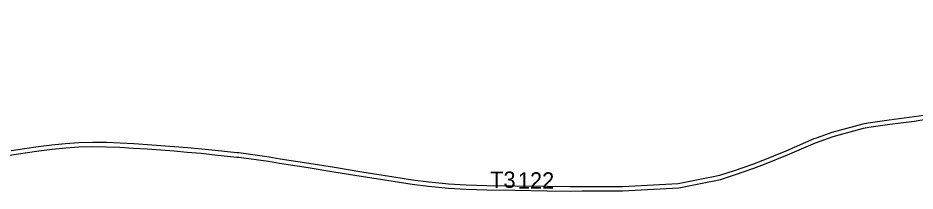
# Model space of a CAD drawing. Extents: x -477001 to -465642, y -1158278 to -1150672.
# Drawn here: x -470657 to -469997, y -1153800 to -1153673 of the extents above; entities that cross this region are included whole.
import ezdxf

# ---------------------------------------------------------------- set-up
doc = ezdxf.new("R2010")
doc.units = 0
for name, color, linetype in [('VPS_id', 7, 'Continuous'), ('VPS_n', 7, 'Continuous'), ('vyvlastneni_n', 7, 'Continuous')]:
    doc.layers.add(name, color=color, linetype=linetype)

msp = doc.modelspace()

# ---------------------------------------------------------------- linework, layer by layer
at = {"layer": 'VPS_n'}
for p, q in [((-470069.83, -1153760.86), (-470071.56, -1153761.53)), ((-470063.02, -1153758.53), (-470069.83, -1153760.86)), ((-470652.22, -1153768.74), (-470662.1, -1153770.15)), ((-470592.07, -1153767.18), (-470582.08, -1153767.55)), ((-470571.91, -1153765.17), (-470581.93, -1153764.55)), ((-470561.91, -1153765.85), (-470571.91, -1153765.17)), ((-470551.93, -1153766.56), (-470561.91, -1153765.85)), ((-470541.93, -1153767.33), (-470551.93, -1153766.56)), ((-470532.45, -1153768.12), (-470541.93, -1153767.33)), ((-470521.96, -1153769.04), (-470532.45, -1153768.12)), ((-470562.12, -1153768.84), (-470552.15, -1153769.55)), ((-470552.15, -1153769.55), (-470542.17, -1153770.32)), ((-470542.17, -1153770.32), (-470532.71, -1153771.11)), ((-470511.98, -1153770.09), (-470521.96, -1153769.04)), ((-470472.42, -1153774.91), (-470494.57, -1153771.77)), ((-470464.16, -1153776.25), (-470472.42, -1153774.91)), ((-470443.18, -1153779.56), (-470464.16, -1153776.25)), ((-470424.21, -1153782.59), (-470443.18, -1153779.56)), ((-470381.15, -1153792.57), (-470367.2, -1153794.75)), ((-470354.83, -1153793.23), (-470366.79, -1153791.78)), ((-470342.66, -1153794.46), (-470354.83, -1153793.23)), ((-470340.28, -1153794.65), (-470342.66, -1153794.46)), ((-470327.5, -1153798.46), (-470312.32, -1153798.89)), ((-470312.32, -1153798.89), (-470291.63, -1153799.22)), ((-470291.63, -1153799.22), (-470267.7, -1153799.53)), ((-470267.7, -1153799.53), (-470250.88, -1153799.74)), ((-470250.86, -1153796.74), (-470267.66, -1153796.53))]:
    msp.add_line(p, q, dxfattribs=at)
for points in [[(-470144.94, -1153792.24), (-470140.23, -1153791.32), (-470129.3, -1153787.64), (-470115.74, -1153783.08), (-470108.03, -1153780.1), (-470091.01, -1153773.14), (-470070.47, -1153764.33), (-470057.45, -1153759.75), (-470035.04, -1153753.64), (-470031.12, -1153752.97), (-470015.72, -1153750.56), (-469997.47, -1153748.33), (-469993.57, -1153747.76), (-469959.11, -1153742.5), (-469955.04, -1153741.64), (-469927.41, -1153736.82), (-469911.9, -1153729.32), (-469906.07, -1153723.14), (-469899.47, -1153716.14), (-469892.68, -1153703.71), (-469880.94, -1153672.67)], [(-469962.14, -1153739.93), (-469994.02, -1153744.79), (-469997.87, -1153745.36), (-470016.13, -1153747.59), (-470031.6, -1153750.01), (-470035.69, -1153750.71), (-470058.34, -1153756.88), (-470063.02, -1153758.53)], [(-470071.56, -1153761.53), (-470092.17, -1153770.37), (-470109.14, -1153777.31), (-470116.76, -1153780.26), (-470130.26, -1153784.8), (-470141, -1153788.41), (-470145.52, -1153789.3)], [(-470669.12, -1153774.05), (-470661.7, -1153773.12), (-470651.8, -1153771.71), (-470641.9, -1153770.29), (-470631.99, -1153768.97), (-470622.04, -1153767.97), (-470612.27, -1153767.24)], [(-470632.34, -1153765.99), (-470642.31, -1153767.32), (-470652.22, -1153768.74)], [(-470612.42, -1153764.24), (-470622.3, -1153764.98), (-470632.34, -1153765.99)], [(-470581.93, -1153764.55), (-470591.99, -1153764.18), (-470602.08, -1153764), (-470612.42, -1153764.24)], [(-470612.27, -1153767.24), (-470602.07, -1153767), (-470592.07, -1153767.18)], [(-470582.08, -1153767.55), (-470572.1, -1153768.16), (-470562.12, -1153768.84)], [(-470532.71, -1153771.11), (-470522.25, -1153772.03), (-470512.3, -1153773.07), (-470496.23, -1153774.79), (-470494.76, -1153774.77), (-470472.87, -1153777.88), (-470464.63, -1153779.21), (-470443.65, -1153782.52)], [(-470494.57, -1153771.77), (-470496.09, -1153771.79), (-470511.98, -1153770.09)], [(-470443.65, -1153782.52), (-470424.69, -1153785.55), (-470404.73, -1153788.78), (-470381.15, -1153792.57)], [(-470366.79, -1153791.78), (-470380.68, -1153789.61), (-470404.25, -1153785.82), (-470424.21, -1153782.59)], [(-470367.2, -1153794.75), (-470355.16, -1153796.21), (-470342.93, -1153797.45), (-470340.49, -1153797.64), (-470327.5, -1153798.46)], [(-470312.25, -1153795.89), (-470327.36, -1153795.46), (-470340.28, -1153794.65)], [(-470250.88, -1153799.74), (-470242.1, -1153799.72), (-470237.45, -1153799.7), (-470212.28, -1153799.63), (-470170.99, -1153797.37), (-470150.05, -1153793.25), (-470144.94, -1153792.24)], [(-470145.52, -1153789.3), (-470150.63, -1153790.31), (-470171.36, -1153794.39), (-470212.37, -1153796.63), (-470237.46, -1153796.7), (-470242.11, -1153796.72), (-470250.86, -1153796.74)], [(-470267.66, -1153796.53), (-470291.59, -1153796.22), (-470312.25, -1153795.89)]]:
    msp.add_lwpolyline(points, dxfattribs=at)
at = {"layer": 'vyvlastneni_n'}
for p, q in [((-470069.83, -1153760.86), (-470071.56, -1153761.53)), ((-470063.02, -1153758.53), (-470069.83, -1153760.86)), ((-470652.22, -1153768.74), (-470662.1, -1153770.15)), ((-470592.07, -1153767.18), (-470582.08, -1153767.55)), ((-470571.91, -1153765.17), (-470581.93, -1153764.55)), ((-470561.91, -1153765.85), (-470571.91, -1153765.17)), ((-470551.93, -1153766.56), (-470561.91, -1153765.85)), ((-470541.93, -1153767.33), (-470551.93, -1153766.56)), ((-470532.45, -1153768.12), (-470541.93, -1153767.33)), ((-470521.96, -1153769.04), (-470532.45, -1153768.12)), ((-470562.12, -1153768.84), (-470552.15, -1153769.55)), ((-470552.15, -1153769.55), (-470542.17, -1153770.32)), ((-470542.17, -1153770.32), (-470532.71, -1153771.11)), ((-470511.98, -1153770.09), (-470521.96, -1153769.04)), ((-470472.42, -1153774.91), (-470494.57, -1153771.77)), ((-470464.16, -1153776.25), (-470472.42, -1153774.91)), ((-470443.18, -1153779.56), (-470464.16, -1153776.25)), ((-470424.21, -1153782.59), (-470443.18, -1153779.56)), ((-470381.15, -1153792.57), (-470367.2, -1153794.75)), ((-470354.83, -1153793.23), (-470366.79, -1153791.78)), ((-470342.66, -1153794.46), (-470354.83, -1153793.23)), ((-470340.28, -1153794.65), (-470342.66, -1153794.46)), ((-470327.5, -1153798.46), (-470312.32, -1153798.89)), ((-470312.32, -1153798.89), (-470291.63, -1153799.22)), ((-470291.63, -1153799.22), (-470267.7, -1153799.53)), ((-470267.7, -1153799.53), (-470250.88, -1153799.74)), ((-470250.86, -1153796.74), (-470267.66, -1153796.53))]:
    msp.add_line(p, q, dxfattribs=at)
for points in [[(-470144.94, -1153792.24), (-470140.23, -1153791.32), (-470129.3, -1153787.64), (-470115.74, -1153783.08), (-470108.03, -1153780.1), (-470091.01, -1153773.14), (-470070.47, -1153764.33), (-470057.45, -1153759.75), (-470035.04, -1153753.64), (-470031.12, -1153752.97), (-470015.72, -1153750.56), (-469997.47, -1153748.33), (-469993.57, -1153747.76), (-469959.11, -1153742.5), (-469955.04, -1153741.64), (-469927.41, -1153736.82), (-469911.9, -1153729.32), (-469906.07, -1153723.14), (-469899.47, -1153716.14), (-469892.68, -1153703.71), (-469880.94, -1153672.67)], [(-469962.14, -1153739.93), (-469994.02, -1153744.79), (-469997.87, -1153745.36), (-470016.13, -1153747.59), (-470031.6, -1153750.01), (-470035.69, -1153750.71), (-470058.34, -1153756.88), (-470063.02, -1153758.53)], [(-470071.56, -1153761.53), (-470092.17, -1153770.37), (-470109.14, -1153777.31), (-470116.76, -1153780.26), (-470130.26, -1153784.8), (-470141, -1153788.41), (-470145.52, -1153789.3)], [(-470669.12, -1153774.05), (-470661.7, -1153773.12), (-470651.8, -1153771.71), (-470641.9, -1153770.29), (-470631.99, -1153768.97), (-470622.04, -1153767.97), (-470612.27, -1153767.24)], [(-470632.34, -1153765.99), (-470642.31, -1153767.32), (-470652.22, -1153768.74)], [(-470612.42, -1153764.24), (-470622.3, -1153764.98), (-470632.34, -1153765.99)], [(-470581.93, -1153764.55), (-470591.99, -1153764.18), (-470602.08, -1153764), (-470612.42, -1153764.24)], [(-470612.27, -1153767.24), (-470602.07, -1153767), (-470592.07, -1153767.18)], [(-470582.08, -1153767.55), (-470572.1, -1153768.16), (-470562.12, -1153768.84)], [(-470532.71, -1153771.11), (-470522.25, -1153772.03), (-470512.3, -1153773.07), (-470496.23, -1153774.79), (-470494.76, -1153774.77), (-470472.87, -1153777.88), (-470464.63, -1153779.21), (-470443.65, -1153782.52)], [(-470494.57, -1153771.77), (-470496.09, -1153771.79), (-470511.98, -1153770.09)], [(-470443.65, -1153782.52), (-470424.69, -1153785.55), (-470404.73, -1153788.78), (-470381.15, -1153792.57)], [(-470366.79, -1153791.78), (-470380.68, -1153789.61), (-470404.25, -1153785.82), (-470424.21, -1153782.59)], [(-470367.2, -1153794.75), (-470355.16, -1153796.21), (-470342.93, -1153797.45), (-470340.49, -1153797.64), (-470327.5, -1153798.46)], [(-470312.25, -1153795.89), (-470327.36, -1153795.46), (-470340.28, -1153794.65)], [(-470250.88, -1153799.74), (-470242.1, -1153799.72), (-470237.45, -1153799.7), (-470212.28, -1153799.63), (-470170.99, -1153797.37), (-470150.05, -1153793.25), (-470144.94, -1153792.24)], [(-470145.52, -1153789.3), (-470150.63, -1153790.31), (-470171.36, -1153794.39), (-470212.37, -1153796.63), (-470237.46, -1153796.7), (-470242.11, -1153796.72), (-470250.86, -1153796.74)], [(-470267.66, -1153796.53), (-470291.59, -1153796.22), (-470312.25, -1153795.89)]]:
    msp.add_lwpolyline(points, dxfattribs=at)

# ---------------------------------------------------------------- texts
at = {"layer": 'VPS_id'}
msp.add_text('122', height=12, dxfattribs=at).set_placement((-470289.4, -1153798.01))
at = {"layer": 'VPS_n'}
msp.add_text('T3', height=12, dxfattribs=at).set_placement((-470309.79, -1153797.43))

doc.saveas('drawing.dxf')
